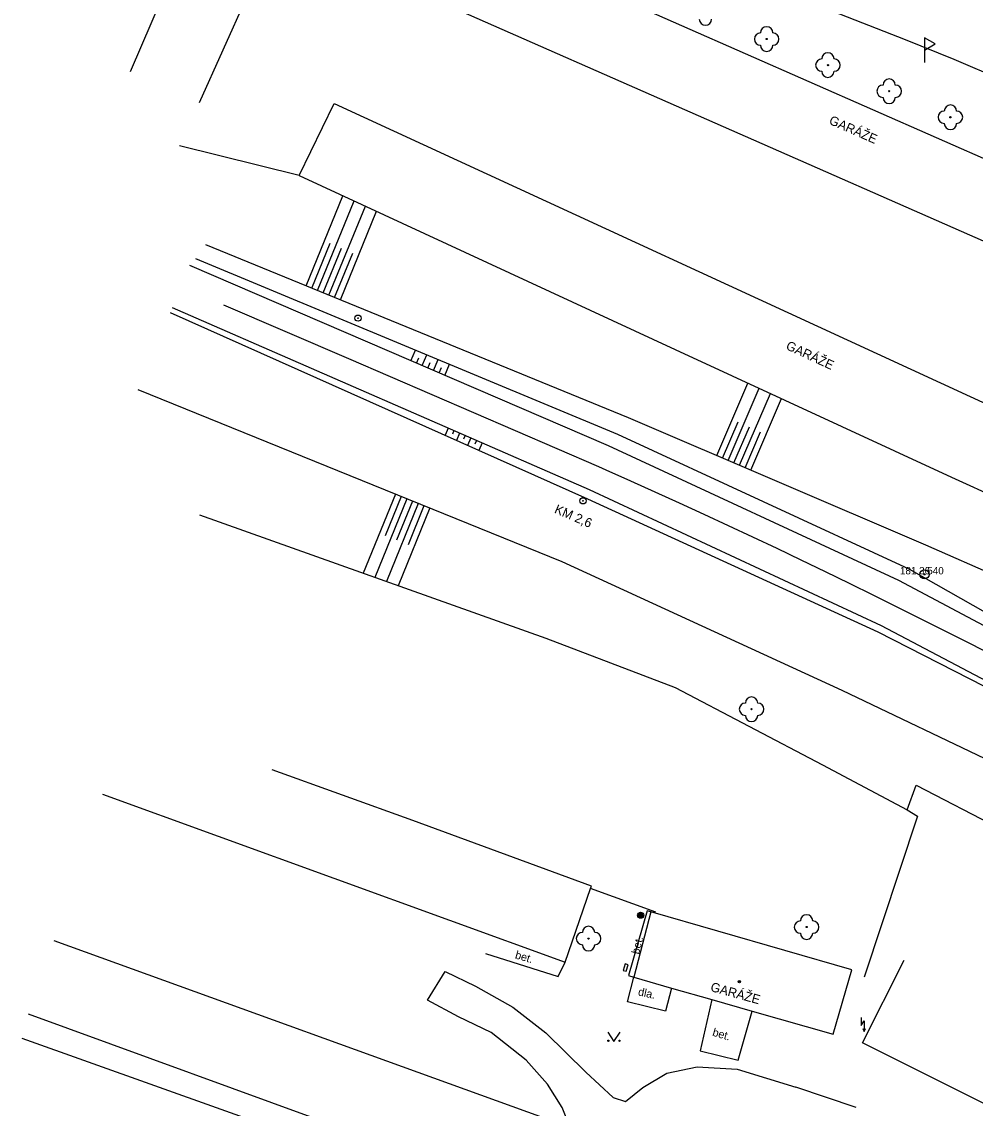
# Model space of a CAD drawing. Extents: x -538441 to -536770, y -1181008 to -1179809.
# Drawn here: x -538329.8 to -538252.4, y -1180911 to -1180822.8 of the extents above; entities that cross this region are included whole.
import ezdxf

# ---------------------------------------------------------------- set-up
doc = ezdxf.new("R2010")
doc.units = 0
for name, color, linetype in [('Vrstva 10', 7, 'Continuous'), ('Vrstva 11', 7, 'Continuous'), ('Vrstva 12', 7, 'Continuous'), ('Vrstva 13', 7, 'Continuous'), ('Vrstva 14', 7, 'Continuous'), ('Vrstva 15', 7, 'Continuous'), ('Vrstva 21', 7, 'Continuous'), ('Vrstva 22', 7, 'Continuous'), ('Vrstva 23', 7, 'Continuous'), ('Vrstva 24', 7, 'Continuous'), ('Vrstva 25', 7, 'Continuous'), ('Vrstva 31', 7, 'Continuous'), ('Vrstva 36', 7, 'Continuous'), ('Vrstva 39', 7, 'Continuous'), ('Vrstva 40', 7, 'Continuous'), ('Vrstva 41', 7, 'Continuous'), ('Vrstva 5', 7, 'Continuous'), ('Vrstva 7', 7, 'Continuous')]:
    doc.layers.add(name, color=color, linetype=linetype)

msp = doc.modelspace()

# ---------------------------------------------------------------- linework, layer by layer
at = {"layer": 'Vrstva 10'}
msp.add_line((-538258.03, -1180824.29), (-538277.975, -1180816.445), dxfattribs=at)
msp.add_lwpolyline([(-538250.159, -1180827.552), (-538254.08, -1180825.887), (-538258.03, -1180824.29)], dxfattribs=at)
at = {"layer": 'Vrstva 11'}
for p, q in [((-538278.72, -1180895.08), (-538279, -1180895)), ((-538271.63, -1180907.14), (-538270.479, -1180903.147)), ((-538287.24, -1180904.92), (-538284, -1180908.1)), ((-538287.11, -1180909.07), (-538288.84, -1180907.12)), ((-538262.05, -1180910.98), (-538266.93, -1180909.33))]:
    msp.add_line(p, q, dxfattribs=at)
for points in [[(-538279, -1180895), (-538280.52, -1180900.25)], [(-538292.15, -1180898.46), (-538286.24, -1180900.34)], [(-538286.24, -1180900.34), (-538285.67, -1180899.18)], [(-538296.85, -1180902.26), (-538295.41, -1180899.94), (-538292.96, -1180901.13), (-538289.93, -1180902.82)], [(-538280.52, -1180900.25), (-538280.1, -1180900.39)], [(-538277.03, -1180901.27), (-538277.52, -1180903.15), (-538280.6, -1180902.39), (-538280.1, -1180900.39)], [(-538288.84, -1180907.12), (-538291.68, -1180904.87), (-538294.32, -1180903.61), (-538296.85, -1180902.26)], [(-538289.93, -1180902.82), (-538287.24, -1180904.92)], [(-538273.759, -1180902.207), (-538274.7, -1180906.36), (-538271.63, -1180907.14)], [(-538284, -1180908.1), (-538281.76, -1180910.16), (-538280.77, -1180910.48), (-538279.36, -1180909.34), (-538277.42, -1180908.18)], [(-538277.42, -1180908.18), (-538274.95, -1180907.67), (-538271.69, -1180907.85)], [(-538271.69, -1180907.85), (-538266.93, -1180909.33)], [(-538285.35, -1180915.47), (-538285.07, -1180913.06), (-538285.9, -1180910.96), (-538287.11, -1180909.07)]]:
    msp.add_lwpolyline(points, dxfattribs=at)
at = {"layer": 'Vrstva 12'}
for centre, radius in [((-538302.488, -1180846.88), 0.25), ((-538302.488, -1180846.88), 0.03), ((-538284.224, -1180861.713), 0.25), ((-538284.224, -1180861.713), 0.03)]:
    msp.add_circle(centre, radius, dxfattribs=at)
at = {"layer": 'Vrstva 13'}
for p, q in [((-538303.242, -1180850.19), (-538313.395, -1180845.817)), ((-538293.092, -1180854.571), (-538303.242, -1180850.19)), ((-538282.946, -1180858.959), (-538293.092, -1180854.571))]:
    msp.add_line(p, q, dxfattribs=at)
for points in [[(-538280.346, -1180860.117), (-538282.338, -1180859.229), (-538282.946, -1180858.959)], [(-538272.411, -1180863.74), (-538274.389, -1180862.823), (-538276.372, -1180861.914), (-538278.357, -1180861.012), (-538280.346, -1180860.117)], [(-538270.435, -1180864.664), (-538272.411, -1180863.74)], [(-538262.568, -1180868.433), (-538264.529, -1180867.48), (-538266.494, -1180866.534), (-538268.463, -1180865.596), (-538270.435, -1180864.664)], [(-538260.609, -1180869.393), (-538262.568, -1180868.433)], [(-538252.812, -1180873.306), (-538254.756, -1180872.317), (-538256.704, -1180871.335), (-538258.655, -1180870.361), (-538260.609, -1180869.393)], [(-538250.872, -1180874.302), (-538252.812, -1180873.306)]]:
    msp.add_lwpolyline(points, dxfattribs=at)
at = {"layer": 'Vrstva 14'}
for p, q in [((-538307.267, -1180835.296), (-538316.977, -1180832.887)), ((-538314.882, -1180840.907), (-538280.541, -1180854.957)), ((-538315.694, -1180842.046), (-538281.41, -1180856.305)), ((-538282.15, -1180857.257), (-538316.152, -1180842.598)), ((-538317.745, -1180846.408), (-538283.864, -1180861.556)), ((-538283.686, -1180860.807), (-538317.557, -1180846.044)), ((-538285.906, -1180866.661), (-538320.334, -1180852.697)), ((-538280.541, -1180854.957), (-538256.396, -1180865.295)), ((-538281.41, -1180856.305), (-538257.75, -1180867.234)), ((-538258.569, -1180868.181), (-538282.15, -1180857.257)), ((-538259.981, -1180871.876), (-538283.686, -1180860.807)), ((-538283.864, -1180861.556), (-538260.267, -1180872.346)), ((-538256.396, -1180865.295), (-538231.59, -1180876.233)), ((-538263.171, -1180877.119), (-538285.906, -1180866.661)), ((-538257.75, -1180867.234), (-538233.699, -1180880.902)), ((-538234.578, -1180880.945), (-538258.569, -1180868.181)), ((-538235.832, -1180884.549), (-538259.981, -1180871.876)), ((-538260.267, -1180872.346), (-538235.975, -1180884.797)), ((-538238.444, -1180888.939), (-538263.171, -1180877.119))]:
    msp.add_line(p, q, dxfattribs=at)
at = {"layer": 'Vrstva 15'}
for p, q in [((-538306.704, -1180844.254), (-538303.712, -1180836.942)), ((-538305.778, -1180844.632), (-538302.804, -1180837.362)), ((-538304.852, -1180845.011), (-538301.894, -1180837.783)), ((-538303.926, -1180845.39), (-538300.986, -1180838.203)), ((-538306.24, -1180844.443), (-538304.748, -1180840.798)), ((-538305.314, -1180844.822), (-538303.832, -1180841.197)), ((-538304.39, -1180845.2), (-538302.916, -1180841.597)), ((-538298.2, -1180850.337), (-538297.83, -1180849.476)), ((-538297.282, -1180850.733), (-538296.906, -1180849.86)), ((-538297.742, -1180850.535), (-538297.554, -1180850.102)), ((-538296.824, -1180850.931), (-538296.634, -1180850.492)), ((-538296.364, -1180851.129), (-538295.982, -1180850.244)), ((-538295.904, -1180851.327), (-538295.712, -1180850.882)), ((-538295.446, -1180851.525), (-538295.058, -1180850.628)), ((-538273.342, -1180858.04), (-538270.822, -1180852.156)), ((-538272.422, -1180858.433), (-538269.914, -1180852.575)), ((-538271.504, -1180858.827), (-538269.006, -1180852.994)), ((-538270.584, -1180859.221), (-538268.098, -1180853.413)), ((-538272.882, -1180858.237), (-538271.626, -1180855.301)), ((-538295.158, -1180855.807), (-538295.414, -1180856.393)), ((-538294.7, -1180856.007), (-538294.828, -1180856.302)), ((-538271.962, -1180858.63), (-538270.712, -1180855.707)), ((-538271.044, -1180859.024), (-538269.798, -1180856.114)), ((-538294.242, -1180856.207), (-538294.5, -1180856.801)), ((-538293.782, -1180856.406), (-538293.914, -1180856.706)), ((-538293.324, -1180856.606), (-538293.588, -1180857.209)), ((-538292.866, -1180856.806), (-538292.998, -1180857.109)), ((-538292.408, -1180857.006), (-538292.674, -1180857.617)), ((-538299.452, -1180861.166), (-538302.062, -1180867.599)), ((-538298.988, -1180861.354), (-538300.29, -1180864.561)), ((-538298.526, -1180861.542), (-538301.118, -1180867.935)), ((-538297.598, -1180861.918), (-538300.176, -1180868.271)), ((-538298.062, -1180861.73), (-538299.354, -1180864.917)), ((-538296.672, -1180862.294), (-538299.232, -1180868.606)), ((-538297.136, -1180862.106), (-538298.42, -1180865.272))]:
    msp.add_line(p, q, dxfattribs=at)
at = {"layer": 'Vrstva 21'}
for radius in [0.375, 0.05]:
    msp.add_circle((-538256.487, -1180867.683), radius, dxfattribs=at)
at = {"layer": 'Vrstva 22'}
for centre in [(-538269.306, -1180824.217), (-538264.332, -1180826.334), (-538259.358, -1180828.451), (-538254.384, -1180830.568), (-538270.535, -1180878.633), (-538266.06, -1180896.32), (-538283.77, -1180897.26)]:
    msp.add_circle(centre, 0.05, dxfattribs=at)
for centre, start, end in [((-538274.28, -1180822.6), 180, 0), ((-538269.306, -1180823.717), 0, 180), ((-538269.806, -1180824.217), 90, 270), ((-538268.806, -1180824.217), 270, 90), ((-538269.306, -1180824.717), 180, 0), ((-538264.832, -1180826.334), 90, 270), ((-538264.332, -1180825.834), 0, 180), ((-538263.832, -1180826.334), 270, 90), ((-538264.332, -1180826.834), 180, 0), ((-538259.858, -1180828.451), 90, 270), ((-538259.358, -1180827.951), 0, 180), ((-538258.858, -1180828.451), 270, 90), ((-538259.358, -1180828.951), 180, 0), ((-538254.384, -1180830.068), 0, 180), ((-538254.884, -1180830.568), 90, 270), ((-538253.884, -1180830.568), 270, 90), ((-538254.384, -1180831.068), 180, 0), ((-538271.035, -1180878.633), 90, 270), ((-538270.535, -1180878.133), 0, 180), ((-538270.035, -1180878.633), 270, 90), ((-538270.535, -1180879.133), 180, 0), ((-538266.56, -1180896.32), 90, 270), ((-538266.06, -1180895.82), 0, 180), ((-538265.56, -1180896.32), 270, 90), ((-538284.27, -1180897.26), 90, 270), ((-538283.77, -1180896.76), 0, 180), ((-538283.27, -1180897.26), 270, 90), ((-538266.06, -1180896.82), 180, 0), ((-538283.77, -1180897.76), 180, 0)]:
    msp.add_arc(centre, 0.5, start, end, dxfattribs=at)
at = {"layer": 'Vrstva 24'}
for p, q in [((-538261.64, -1180903.674), (-538261.64, -1180904.301)), ((-538261.64, -1180904.301), (-538261.39, -1180903.925)), ((-538261.499, -1180904.555), (-538261.39, -1180904.8)), ((-538261.39, -1180903.925), (-538261.39, -1180904.8)), ((-538261.39, -1180904.8), (-538261.279, -1180904.555))]:
    msp.add_line(p, q, dxfattribs=at)
msp.add_lwpolyline([(-538280.96, -1180899.84), (-538280.707, -1180899.915), (-538280.547, -1180899.375), (-538280.8, -1180899.3), (-538280.96, -1180899.84)], dxfattribs=at)
at = {"layer": 'Vrstva 25'}
for radius in [0.25, 0.2, 0.15, 0.1, 0.05]:
    msp.add_circle((-538279.54, -1180895.36), radius, dxfattribs=at)
at = {"layer": 'Vrstva 31'}
msp.add_line((-538256.48, -1180825.11), (-538256.48, -1180826.11), dxfattribs=at)
msp.add_lwpolyline([(-538256.48, -1180824.11), (-538256.48, -1180825.11), (-538255.614, -1180824.61)], close=True, dxfattribs=at)
at = {"layer": 'Vrstva 36'}
msp.add_lwpolyline([(-538282.21, -1180904.85), (-538281.71, -1180905.6), (-538281.21, -1180904.85)], dxfattribs=at)
for centre in [(-538282.16, -1180905.55), (-538281.261, -1180905.55)]:
    msp.add_circle(centre, 0.05, dxfattribs=at)
at = {"layer": 'Vrstva 39'}
for radius in [0.09, 0.0398]:
    msp.add_circle((-538271.521, -1180900.764), radius, dxfattribs=at)
at = {"layer": 'Vrstva 5'}
for p, q in [((-538312.48, -1180807.08), (-538320.99, -1180826.89)), ((-538306.57, -1180809.71), (-538315.39, -1180829.39)), ((-538298.62, -1180813.24), (-538223.82, -1180846.17)), ((-538301.07, -1180818.89), (-538226.27, -1180851.82)), ((-538307.267, -1180835.296), (-538304.43, -1180829.45)), ((-538304.43, -1180829.45), (-538224.84, -1180866.12)), ((-538307.267, -1180835.296), (-538276.739, -1180849.427)), ((-538276.739, -1180849.427), (-538254.287, -1180859.783)), ((-538254.287, -1180859.783), (-538228.345, -1180871.737)), ((-538298.03, -1180887.67), (-538309.45, -1180883.56)), ((-538323.23, -1180885.53), (-538285.67, -1180899.18)), ((-538283.53, -1180892.99), (-538298.03, -1180887.67)), ((-538278.72, -1180895.08), (-538280.1, -1180900.39)), ((-538262.4, -1180899.79), (-538278.72, -1180895.08)), ((-538327.2, -1180897.4), (-538286.18, -1180912.24)), ((-538261.52, -1180905.73), (-538258.151, -1180899.003)), ((-538263.91, -1180905.03), (-538262.4, -1180899.79)), ((-538288.31, -1180918.28), (-538329.26, -1180903.4)), ((-538329.8, -1180905.35), (-538288.85, -1180919.909)), ((-538213.19, -1180929.94), (-538261.52, -1180905.73))]:
    msp.add_line(p, q, dxfattribs=at)
for points in [[(-538285.67, -1180899.18), (-538283.603, -1180893.2), (-538283.53, -1180892.99)], [(-538280.1, -1180900.39), (-538277.03, -1180901.27), (-538273.759, -1180902.207), (-538270.479, -1180903.147), (-538263.91, -1180905.03)]]:
    msp.add_lwpolyline(points, dxfattribs=at)
at = {"layer": 'Vrstva 7'}
for p, q in [((-538315.373, -1180862.861), (-538287.252, -1180872.87)), ((-538287.252, -1180872.87), (-538276.747, -1180876.879)), ((-538276.747, -1180876.879), (-538264.773, -1180883.147)), ((-538264.773, -1180883.147), (-538257.889, -1180886.802)), ((-538257.889, -1180886.802), (-538257.16, -1180884.813)), ((-538257.16, -1180884.813), (-538244.055, -1180891.572)), ((-538278.32, -1180895.1), (-538283.603, -1180893.2))]:
    msp.add_line(p, q, dxfattribs=at)
for points in [[(-538257.889, -1180886.802), (-538257.06, -1180887.33)], [(-538257.06, -1180887.33), (-538261.4, -1180900.38)]]:
    msp.add_lwpolyline(points, dxfattribs=at)

# ---------------------------------------------------------------- texts
at = {"layer": 'Vrstva 22'}
msp.add_text('181 36 ', height=0.6, dxfattribs=at).set_placement((-538258.487, -1180867.683))
at = {"layer": 'Vrstva 23'}
msp.add_text(' 540', height=0.6, dxfattribs=at).set_placement((-538256.487, -1180867.683))
at = {"layer": 'Vrstva 40'}
for s, rotation, p in [('bet.', 75.86481, (-538279.674, -1180898.572)), ('bet.', 343.72613, (-538289.786, -1180898.857)), ('dla.', 347.87291, (-538279.789, -1180901.861)), ('bet.', 343.72613, (-538273.756, -1180905.132))]:
    msp.add_text(s, height=0.65, rotation=rotation, dxfattribs=at).set_placement(p)
at = {"layer": 'Vrstva 41'}
for s, rotation, p in [('GARÁŽE', 336.23896, (-538264.306, -1180831.081)), ('GARÁŽE', 335.26276, (-538267.806, -1180849.373)), ('KM 2,6', 336.6, (-538286.604, -1180862.663)), ('GARÁŽE', 344.58156, (-538273.925, -1180901.504))]:
    msp.add_text(s, height=0.75, rotation=rotation, dxfattribs=at).set_placement(p)

doc.saveas('drawing.dxf')
